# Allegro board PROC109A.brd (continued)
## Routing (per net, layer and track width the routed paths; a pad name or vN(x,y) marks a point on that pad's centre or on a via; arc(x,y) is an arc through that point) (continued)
VBAT_XDS: length 4.1
  BOTTOM w0.178: 18.11,-43.99 U37.68
  BOTTOM w0.33: R249.2 C208.1 17.42,-44.68 18.11,-43.99
VBUS_DETECT: length 1.7
  TOP w0.135: R113.1 14.12,-46.49 U20.4
VBUS_TYPEC: length 6.9
  TOP w0.254: J10.B4 19.77,-58.18 J10.A9 19.77,-55.97 v1(19.61,-55.8) ; J10.B9 17.27,-58.18 J10.A4 17.27,-56.17 v1(16.73,-55.63) ; C70.1 20.43,-54.86
  BOTTOM w0.381: J10.B4 19.72,-57.71 ; J10.B9 17.32,-57.71
  vias: v1(15.46,-54.36) v1(15.46,-55.63) v1(16.48,-54.33) v1(19.68,-50.8) v1(19.68,-52.07) v1(19.84,-53.09) v1(21.34,-52.07)
VBUS_XDS_USB: length 43.5
  TOP w0.203: U24.10 U24.1
  TOP w0.254: TP27.1 2.58,-42.64 8.06,-42.64 v1(9.14,-41.55) ; 9.73,-51.28 9.49,-51.52 U24.10
  TOP w0.381: J20.1 6.48,-52.29 6.81,-51.97
  BOTTOM w0.33: U38.6 11.57,-42.02 ; 10.16,-42.16 11.32,-43.32 U38.4
  BOTTOM w0.381: R222.2 R219.1
  BOTTOM w0.635: R222.2 15.49,-31.27
  BOTTOM w0.762: v1(8.08,-50.85) v1(9.35,-50.85) 11.15,-49.05 11.15,-45.31 9.14,-43.31 v1(9.14,-41.55) 10.16,-40.54 10.16,-38.79 9.37,-38 9.37,-34.09 10.77,-32.69 14.07,-32.69 15.49,-31.27
VCC3V3_TA: length 96.8
  TOP w0.178: v1(28.57,-23.02) U4.2 29.37,-22.73 29.54,-22.56
  TOP w0.203: v1(5.08,-32.72) 5.49,-33.12 TP49.1
  TOP w0.33: v1(30.96,-20.6) C5.1 U4.1
  TOP w0.381: R34.2 26.37,-25.87 v1(26.37,-26.62) ; U9.5 4.21,-28.87 v1(3.94,-28.6) ; R28.2 26.39,-24.35 v1(26.39,-23.57) ; v1(10.4,-27.2) v1(10.4,-25.32) v1(10.4,-23.44) v1(10.4,-21.56) v1(10.4,-19.68) ; v1(5.08,-32.72) 4.65,-32.72 v1(4.01,-32.08) 4.01,-31.11 4.31,-30.82 U9.8
  TOP w0.508: v1(26.39,-23.57) 26.39,-22.87 R17.2 ; R70.2 R67.2 R53.2 ; R34.2 R28.2
  L03_SIG1 w0.381: v1(10.4,-25.32) 11.3,-25.32 12.24,-24.38 12.85,-24.38 13.67,-23.57 14.99,-23.57 15.29,-23.27 18.78,-23.27 19.08,-23.57 v1(26.39,-23.57) 28.02,-23.57 v1(28.57,-23.02) ; v1(6.55,-40.36) 4.01,-37.82 v1(4.01,-32.08) ; v1(5.08,-32.72) 4.45,-32.08 v1(4.01,-32.08) ; v1(4.01,-32.08) 3.94,-32 v1(3.94,-28.6) 8.18,-28.6 9.58,-27.2 v1(10.4,-27.2)
  L04_PWR1 w0.381: v1(7.49,-48.64) v1(9.27,-48.64) 9.27,-47.45 v1(9.3,-47.42)
  BOTTOM w0.254: U26.15 23.72,-19.92 23.6,-20.04 ; U26.14 23.85,-20.42 23.75,-20.32 ; C146.1 7.57,-38.86 ; C155.1 7.57,-39.75
  BOTTOM w0.33: U28.5 C88.1 33.45,-22.29 ; C85.1 22.43,-21.29 v1(22.53,-21.39)
  BOTTOM w0.381: v1(7.49,-48.64) 8.33,-48.64 C243.1 8.44,-48.64 v1(9.27,-48.64) 9.27,-48.02 9.3,-47.99 v1(9.3,-47.42) ; R209.2 v1(10.4,-27.2)
  BOTTOM w0.508: 33.45,-22.29 32.65,-22.29 v1(30.96,-20.6) ; R182.1 12.07,-20.05 11.71,-19.68 v1(10.4,-19.68) R178.1 ; R196.2 12.07,-23.88 11.63,-23.44 v1(10.4,-23.44) R189.2 ; R186.1 v1(10.4,-21.56) 11.84,-21.56 12.07,-21.8 R187.1 ; R197.2 v1(10.4,-25.32) 11.71,-25.32 12.07,-25.69 R202.2 ; R191.2 24.94,-25.19 v1(26.37,-26.62)
VCC3V3_XDS: length 93.8
  TOP w0.254: v1(37.57,-55.27) 37.57,-56.67 TP35.1 ; v1(27.28,-44.58) 27.28,-44.07 27.52,-43.83 R108.2 ; C44.1 U16.7 ; R109.2 v1(29.84,-43.05)
  TOP w0.33: v1(67.85,-50) 68.12,-49.73 68.33,-49.73 C60.1 68.44,-49.87 68.44,-50.19 68.09,-50.54 U25.16 ; v1(25.07,-40.53) C44.1
  TOP w0.381: 38.86,-41.2 40.28,-42.62 40.28,-52.55 v1(37.57,-55.27) ; R101.2 v1(24.99,-41.55) ; R100.2 v1(23.52,-41.55) ; v1(25.22,-48.26) 25.22,-47.02 25.43,-46.81 ; R98.2 v1(20.5,-41.55) ; R99.2 v1(22.05,-41.55)
  L05_GND2 w0.381: v1(58.81,-52.86) 59.29,-52.37 66.52,-52.37 67.85,-51.04 v1(67.85,-50)
  BOTTOM w0.178: v1(17.78,-34.98) 17.78,-35.01 17.96,-35.19 U37.90 ; U37.52 25.5,-47.8 25.63,-47.93 ; C191.1 35.81,-43.59 35.81,-43.59 U37.28 ; U37.79 17.94,-39.59 ; 27.1,-30.23 U37.113 ; U37.51 25.9,-47.77 ; U37.16 35.75,-38.79 35.75,-38.79 ; v1(30.7,-32.44) 30.7,-32.43 U37.122 ; U42.8 66.21,-53.71 65.91,-53.4 65.91,-53.01 65.73,-52.83 C260.1 ; v1(27.28,-44.58) 27.55,-44.85 27.55,-45.73 27.5,-45.78 U37.47 ; U37.26 36.08,-42.79 C180.1 ; C121.1 36.67,-35.19 U37.7 ; v1(22.02,-29.95) 22.3,-30.23 U37.101 ; 17.73,-43.59 U37.69 ; 35.94,-35.48 35.84,-35.59 U37.8 ; 30.71,-47.9 30.7,-47.9 U37.39
  BOTTOM w0.254: U45.16 36.23,-55.66 36.44,-55.87 C262.1 v1(37.57,-55.27) ; 14.82,-42.02 14.39,-42.02 U38.1 ; v1(17.04,-42.39) 17.04,-42.9 17.73,-43.59
  BOTTOM w0.33: 17.94,-39.59 17.88,-39.65 C154.1 16.47,-39.65 v1(15.88,-40.24) ; 35.75,-38.79 36.4,-38.79 C151.1 36.98,-38.81 v1(36.98,-38.81) ; v1(31.62,-47.96) 31.62,-48.54 31.45,-48.72 C240.1 30.71,-47.9 ; 27.1,-30.23 26.95,-30.08 C104.1 27.51,-29.44 v1(27.51,-29.44) ; 38.44,-34.62 v1(36.68,-34.62) C121.1 ; v1(58.81,-52.86) 59.35,-52.86 59.48,-52.73 64.24,-52.73 64.34,-52.83 C260.1 ; v1(25.22,-48.26) 25.5,-48.54 C242.1 26.09,-47.96 25.9,-47.77 ; v1(17.04,-42.39) C181.1 C182.1 15.35,-41.71 15.8,-41.25 R246.1
  BOTTOM w0.381: v1(15.93,-46.58) 15.73,-46.58 15.35,-46.2 R249.1 ; 38.44,-34.62 38.7,-34.62 R235.1
  vias: v1(14.61,-40.24) v1(14.61,-41.51) v1(36.14,-44.2) v1(36.17,-41.96)
VCC_5V0_CAN: length 4.2
  TOP w0.203: v1(165.84,-52.02) 164.92,-52.02 TP50.1
  BOTTOM w0.254: v1(165.84,-52.02) R270.2
  BOTTOM w0.33: U44.3 C257.1 R270.2
VDD_1V1: length 25.7
  TOP w0.254: U19.6 v1(144.35,-45.89) C55.1 ; v1(133.99,-45.48) 133.99,-45.49 133.98,-45.5 C56.1 134.64,-46.03 134.78,-45.89 U19.31 ; C17.1 v1(144.35,-26.84) U7.6 ; v1(138.07,-32.18) 137.52,-32.18 C34.1 137.51,-31.78 138.18,-31.11 U7.39 ; v1(138.07,-51.21) 138.06,-51.22 C61.1 137.51,-50.57 138.18,-49.89 U19.39 ; v1(133.99,-26.43) 133.99,-26.44 133.98,-26.45 C19.1 134.64,-26.98 134.78,-26.84 U7.31
  TOP w0.381: TP30.1 125.19,-46.22 125.19,-46.46 125.23,-46.5 125.23,-46.56 125.2,-46.59 125.21,-47.38 125.19,-47.38 v1(125.19,-47.42)
  BOTTOM w0.229: U39.9 125.49,-44.39 125.73,-44.63 ; 125.6,-45.01 125.48,-44.89 U39.10
  BOTTOM w0.254: v1(133.99,-26.43) 133.96,-26.45 C97.1 ; C113.1 138.02,-32.23 v1(138.07,-32.18)
  BOTTOM w0.33: C96.1 144.34,-26.85 v1(144.35,-26.84) C17.1 ; C217.1 144.34,-45.9 v1(144.35,-45.89) C55.1 ; C228.1 134,-46.05 C56.1 133.98,-45.49 v1(133.99,-45.48) ; C256.1 138,-51.28 v1(138.07,-51.21) ; C98.1 133.96,-28.06 C97.1 ; C229.1 126.19,-47.19
  BOTTOM w0.508: C222.1 125.7,-46.05
  vias: v1(125.19,-48.69) v1(126.46,-48.69)
VDD_1V1_SS: length 1.7
  BOTTOM w0.203: C183.1 126.1,-43.39 U39.7
VDD_1V8: length 84.1
  TOP w0.203: TP5.1 63.58,-21.67 40.82,-21.67 37.83,-18.68 33.24,-18.68 32.33,-19.58 31.29,-19.58 30.73,-19.02 29.9,-19.02 26.9,-22.02 25.21,-22.02 24.85,-22.38 23.83,-22.38 23.55,-22.1 22.92,-22.1 19.94,-25.07 v1(19.94,-26.75)
  TOP w0.254: v1(66.17,-23.37) 66.17,-23.75 R30.2 65.1,-23.48 v1(65.1,-23.36) 64.69,-23.36 R29.2 ; C30.2 76.61,-32.74 76.87,-33.01 U11.5
  TOP w0.305: U18.F14 79.35,-42.27 v2(79.35,-41.84)
  TOP w0.33: v1(77.37,-32.21) 77.37,-32.18 77.04,-31.85 C30.2
  TOP w0.381: v1(92.18,-44.12) v1(92.99,-44.12)
  L03_SIG1 w0.152: 77.33,-41.29 77.44,-41.19 78.7,-41.19 v2(79.35,-41.84)
  L03_SIG1 w0.254: 77.33,-41.29 73.11,-41.29 72.71,-40.89 71.35,-40.89 68.88,-43.36 v1(68.3,-43.36)
  L03_SIG1 w0.381: v1(65.1,-23.36) 65.11,-23.37 v1(66.17,-23.37)
  L04_PWR1 w0.254: v1(92.18,-44.12) 92.04,-43.99 92.04,-40.73 91.31,-40
  L04_PWR1 w0.508: v1(77.37,-32.21) 77.06,-32.51 v1(77.06,-33.63)
  BOTTOM w0.135: v1(91.72,-46.28) v1(92.99,-46.28)
  BOTTOM w0.305: C162.1 78.63,-41.31 78.63,-41.31 79.15,-41.84 v2(79.35,-41.84)
  BOTTOM w0.381: R198.1 v1(19.94,-26.75) ; FB1.1 77.37,-31.46 v1(77.37,-32.21) 78.09,-32.93 FB2.1
  BOTTOM w0.508: v1(77.06,-33.63) 77.14,-33.56 FB2.1
  vias: v1(64.9,-22.1) v1(66.17,-22.1) v1(68.76,-49.23)
VDD_1V8_CT: length 3.8
  BOTTOM w0.254: U27.5 17.74,-16.86 18.71,-15.89 C80.1
VDD_1V8_ENABLE: length 31.4
  TOP w0.254: U10.8 42.79,-30.57 v1(42.55,-30.81) 39.29,-30.81 38.81,-30.33 38.81,-24.71 41.05,-22.48 56.55,-22.48 57.07,-23 R31.1
  BOTTOM w0.381: R224.1 v1(42.55,-30.81)
VDD_1V8_R: length 1
  TOP w0.33: 62.61,-26.43 U5.1 ; C20.1 64.67,-26.31
VDD_1V8_SENSE: length 5.9
  BOTTOM w0.135: U27.10 19.57,-21.6 19.94,-21.97 R198.2 R199.1
VDD_2V5: length 21.6
  TOP w0.254: U19.3 v1(144.35,-47.39) C58.1 ; C11.1 v1(144.35,-25.34) U7.9 ; U19.9 v1(144.35,-44.39) C53.1 ; C23.1 v1(144.35,-28.34) U7.3
  TOP w0.381: v1(125.24,-36.7) 124.54,-36.7 123.16,-35.33 TP20.1 R81.2
  BOTTOM w0.229: U33.10 125.48,-34.17 125.6,-34.29 ; 125.73,-33.91 125.49,-33.67 U33.9
  BOTTOM w0.33: C107.1 145.03,-29 144.91,-28.88 144.95,-28.84 C23.1 v1(144.35,-28.34) 143.8,-28.34 C100.1 ; v1(144.32,-49) 144.68,-48.64 C238.1 145.03,-47.98 144.95,-47.89 C58.1 v1(144.35,-47.39) 144.32,-47.42 C231.1 ; C130.1 126.28,-36.47 ; C11.1 v1(144.35,-25.34) ; C53.1 v1(144.35,-44.39)
  BOTTOM w0.381: v1(144.22,-29.97) 144.6,-29.59 C107.1
  BOTTOM w0.508: C125.1 125.71,-35.33 125.7,-35.33
  vias: v1(125.24,-37.97) v1(126.46,-37.97)
VDD_2V5_PG: length 20.2
  TOP w0.203: v1(115.7,-35.31) 119.17,-35.31 119.19,-35.33 R81.1
  TOP w0.254: v1(120.55,-33.54) 119.78,-34.31 R81.1
  BOTTOM w0.203: v1(120.55,-33.54) 121.34,-33.54 121.34,-33.32 121.49,-33.17 U33.3 ; v1(115.7,-35.31) 115.7,-39.62 117.98,-41.91 120.37,-41.91 121.35,-42.89 U39.5
VDD_2V5_SS: length 1.7
  BOTTOM w0.203: C111.1 126.1,-32.67 U33.7
VDD_CORE_0V85: length 122.9
  TOP w0.102: 81.38,-44.81 80.89,-44.33 U18.J10
  TOP w0.152: U18.R12 83.89,-43.3 83.41,-42.82 ; U18.R10 83.89,-44.33 v2(83.37,-44.86) 82.89,-44.38 U18.N10
  TOP w0.178: U18.J12 80.7,-43.09 v2(80.41,-42.77)
  TOP w0.254: v2(85.36,-41.77) 85.39,-41.74 U18.V16 ; TP23.1 56.49,-38.1 v1(56.49,-39.75) ; C48.1 56.62,-42.42 v1(56.49,-42.29) ; U18.L9 v2(81.89,-45.28) ; C49.1 57.76,-42.9 v1(57.76,-42.29)
  TOP w0.305: v2(81.39,-44.83) 81.38,-44.81 U18.J9 ; U18.L13 81.5,-42.82 v2(81.46,-42.77) 81.39,-42.71 U18.K14 ; U18.H15 80.37,-41.79 v2(79.87,-41.79) ; U18.H8 80.41,-45.3 v2(80.41,-44.83) ; U18.K11 81.39,-43.37 v2(81.4,-43.36) 80.94,-43.36 U18.J12 ; U18.N9 82.88,-44.82 v2(82.88,-45.28) 82.85,-45.31 U18.M8 ; v2(79.91,-45.86) 79.89,-45.87 U18.G6 U18.G5 ; U18.R9 83.89,-45.22 v2(83.94,-45.26) 83.45,-45.26 U18.P8 ; U18.R13 83.41,-42.82 v2(83.37,-42.77) 83.39,-42.75 U18.P14 ; v2(80.41,-44.27) 80.45,-44.31 U18.J10 ; U18.F11 79.39,-44.26 v2(79.41,-44.27) 79.45,-44.31 U18.G10 ; v2(82.39,-42.77) U18.M14
  TOP w0.508: v1(51.26,-50.16) R130.1 C62.1 ; 55.33,-39.88 55.08,-40.13 R96.1 55.08,-42.04 55.46,-42.42
  L03_SIG1 w0.254: v1(23.22,-18.57) 27.55,-18.57 31.24,-22.26 31.24,-27 35.51,-31.27 36.68,-31.27 39.45,-34.04 54.97,-34.04 56.49,-35.56 v1(56.49,-39.75)
  L04_PWR1 w0.102: v2(83.37,-42.77) 83.92,-42.77 84.4,-42.29
  L04_PWR1 w0.254: v1(79.35,-52.12) 78.84,-52.12 78.26,-52.7 72.77,-52.7 70.84,-50.77 70.84,-49.4 69.93,-48.49 63.7,-48.49 63.37,-48.82 52.6,-48.82 v1(51.26,-50.16)
  L04_PWR1 w0.305: v2(85.36,-41.77) 85.25,-41.77 84.73,-42.29 84.4,-42.29
  BOTTOM w0.254: v2(81.4,-43.36) 81.4,-42.78 v2(81.46,-42.77) 81.56,-42.87 C187.1
  BOTTOM w0.305: v2(81.39,-44.83) 81.5,-44.73 C199.1 ; C211.1 83.32,-44.91 v2(83.37,-44.86) ; C211.1 83.84,-45.36 v2(83.94,-45.26) ; C211.1 82.97,-45.36 v2(82.88,-45.28) 82.8,-45.36 C212.1 81.98,-45.36 v2(81.89,-45.28) ; C214.1 80.15,-46.1 v2(79.91,-45.86) 79.91,-46.78 C227.1 ; C187.1 82.29,-42.87 v2(82.39,-42.77) 82.5,-42.87 C186.1 83.26,-42.87 v2(83.37,-42.77) ; v2(80.41,-42.77) 80.51,-42.87 C188.1 81.36,-42.87 v2(81.46,-42.77) ; v2(80.41,-44.27) v2(80.41,-44.83) 80.47,-44.77 C200.1
  BOTTOM w0.33: C227.1 79.67,-46.79 79.65,-46.8 79.65,-46.8 79.36,-47.09 79.36,-47.1 79.2,-47.25 79.2,-47.52 ; v2(85.36,-41.77) 85.36,-41.66 C165.1 ; v2(79.41,-44.27) 79.47,-44.34 C201.1 80.35,-44.34 v2(80.41,-44.27) ; C163.1 79.96,-41.7 v2(79.87,-41.79)
  BOTTOM w0.381: v1(80.11,-51.59) 79.91,-51.38 C255.1 79.15,-51.92 v1(79.35,-52.12) ; v1(74.8,-38.91) 74.52,-38.63 C136.1 74.52,-38.2 v1(73.74,-38.2)
  BOTTOM w0.508: C234.1 79.2,-47.52 ; v1(23.22,-18.57) 22.61,-17.96 R176.2
  vias: v1(56.49,-41.02) v1(57.76,-39.75) v1(57.76,-41.02) v1(59.03,-39.75) v1(59.03,-41.02) v1(59.03,-42.29) v1(60.3,-39.75) v1(60.3,-41.02) v1(60.3,-42.29) v1(76.2,-38.73) v1(80.14,-49.4) v1(80.06,-50.39) v1(80.8,-52.12)
VDD_CORE_0V85_EN: length 36.4
  TOP w0.254: R127.1 48.68,-50.15 48.94,-49.89 v1(48.94,-49.43)
  TOP w0.381: v1(62.41,-23.77) R29.1 63.23,-24.8 62.91,-25.13 U5.3
  BOTTOM w0.203: v1(62.41,-23.77) 61.39,-23.77 60.19,-24.98 60.19,-32.85 49.71,-43.33 49.71,-45.77 48.94,-46.54 v1(48.94,-49.43)
VDD_CORE_0V85_FB: length 4.4
  TOP w0.254: U21.2 49.64,-47.31 49.64,-47.31 49.64,-48.75 R124.1 R130.2 C62.2
VDD_CORE_0V85_H_SENSE: length 5.9
  TOP w0.135: v1(20.47,-16.54) 21.3,-16.54 R6.1
  BOTTOM w0.135: U27.6 19.5,-19.6 19.68,-19.42 19.68,-17.32 v1(20.47,-16.54) 21.28,-16.54 R175.2
VDD_CORE_0V85_L_SENSE: length 5.1
  TOP w0.135: R6.2 20.82,-17.61 v1(20.47,-17.96)
  BOTTOM w0.135: U27.7 19.5,-20.1 20.04,-19.56 20.04,-18.39 v1(20.47,-17.96) R176.1
VDD_CORE_0V85_PG: length 62
  TOP w0.254: R112.1 U21.8 ; Q3.3 v1(3.01,-41.85)
  TOP w0.381: v1(42.8,-43.31) 42.8,-45.24 43.37,-45.81 R112.1
  L03_SIG1 w0.381: v1(42.8,-43.31) 41.22,-43.31 38.57,-40.66 38.57,-34.79 36.82,-33.03 32.27,-33.03 31.5,-33.8 27.37,-33.8 26.97,-33.41 21.53,-33.41 21.24,-33.7 15.39,-33.7 15,-33.3 12.72,-33.3 7.11,-38.92 7.11,-40.77 6.6,-41.27 3.59,-41.27 v1(3.01,-41.85)
VDD_CORE_0V85_R: length 3.8
  TOP w0.254: 53.85,-42.42 53.32,-42.95 C50.1
  TOP w0.508: 53.72,-39.88 54.1,-40.26 R96.2 54.1,-42.17 53.85,-42.42
VDD_CORE_0V85_SW: length 4.8
  TOP w0.254: 50.56,-44.41 50.56,-44.54 50.14,-44.96 U21.6
  TOP w0.762: 50.56,-44.41 L2.1
VDDA_1P8_USB0: length 6.6
  TOP w0.152: U18.U15 84.89,-41.88 v2(85.36,-42.35)
  TOP w0.254: TP47.1 92.2,-40.61 v1(92.53,-40.94)
  BOTTOM w0.127: C177.1 86.69,-42.38
  BOTTOM w0.152: v2(85.36,-42.35) 85.73,-42.72 86.35,-42.72 86.69,-42.38
  BOTTOM w0.254: FB5.2 90.56,-42.1 91.24,-41.43 91.62,-41.43 92.1,-40.94 v1(92.53,-40.94)
  BOTTOM w0.33: C176.1 C177.1
VDDA_1V8: length 105.6
  TOP w0.254: v1(32.59,-17.98) 34.14,-17.98 TP40.1
  TOP w0.305: U18.F18 79.82,-40.32 v2(79.85,-40.35) ; U18.H14 79.93,-42.32 v2(79.89,-42.35)
  TOP w0.33: v1(32.59,-17.98) C4.1 32.57,-17.4 31.91,-16.74 U1.5
  TOP w0.381: v1(12.82,-22.13) 12.59,-22.13 12.21,-21.75 R15.2
  L03_SIG1 w0.381: v1(12.82,-22.13) 12.82,-20.44 14.73,-18.53 21.7,-18.53 22.25,-17.98 v1(32.59,-17.98) 32.59,-27.33 34.04,-28.78 35.48,-28.78 36.09,-28.17 37.21,-28.17 38.33,-29.29 49.84,-29.29 50.2,-29.65 55.61,-29.65 56.98,-31.02 71.66,-31.02 74.93,-34.29 77.55,-34.29 78.28,-33.55 v1(80.59,-33.55) 79.68,-34.47 79.68,-36.3 v1(79.96,-36.58)
  L05_GND2 w0.203: v2(79.89,-42.35) 80.27,-41.97 80.27,-41.21 79.85,-40.79 v2(79.85,-40.35)
  BOTTOM w0.305: C153.1 78.7,-39.19 79.05,-39.54 79.05,-39.7 79.69,-40.35 v2(79.85,-40.35)
  BOTTOM w0.33: 79.4,-35.48 C126.1 ; 79.33,-36.86 78.7,-37.49 C135.1 C144.1 C153.1
  BOTTOM w0.381: 79.32,-36.86 79.33,-36.86 C126.1
  BOTTOM w0.508: C126.1 79.33,-34.84 79.71,-34.47 79.69,-34.45 FB2.2 79.7,-33.55 v1(80.59,-33.55)
VDDA_3P3_USB0: length 12.8
  TOP w0.152: v2(84.42,-41.83) 84.89,-41.35 U18.U16
  TOP w0.254: TP45.1 90.22,-38.84 v1(89.81,-38.84)
  L03_SIG1 w0.254: v1(89.81,-38.84) 88.9,-38.84 86.4,-41.34 84.97,-41.34 84.48,-41.83 v2(84.42,-41.83)
  BOTTOM w0.152: C178.1 84.85,-41.38 84.42,-41.81 v2(84.42,-41.83)
  BOTTOM w0.33: C156.1 87.59,-39.62 87.27,-39.93 C157.1
  BOTTOM w0.508: v1(89.81,-38.84) 89.65,-39 FB4.2 89,-39.78 88.84,-39.62 C156.1
VDDA_3V3: length 19.1
  TOP w0.102: v2(80.89,-42.3) 81.12,-42.08 81.13,-42.08 U18.K15
  TOP w0.254: v1(70.79,-37.24) 70.79,-37.22 70.38,-36.81 70.38,-35.76 TP43.1
  L03_SIG1 w0.152: v1(70.79,-37.24) 71.25,-37.69 77.29,-37.69 79.28,-39.68 79.28,-40.44 80.51,-41.68 80.51,-41.93 80.88,-42.3 v2(80.89,-42.3)
  BOTTOM w0.305: v2(80.89,-42.3) 80.6,-42.3 C174.1
  BOTTOM w0.33: FB3.2 C142.1
  BOTTOM w0.508: FB3.2 71.3,-38.19 70.79,-37.68 v1(70.79,-37.24)
VDDA_ADC: length 18.9
  TOP w0.203: v1(80.39,-32.05) 80.39,-32.69 TP48.1
  TOP w0.305: U18.G17 U18.H17 80.41,-40.8 v2(80.41,-40.35)
  L03_SIG1 w0.381: v1(80.39,-32.05) 81.45,-33.12 81.45,-34.08 80.79,-34.74 80.79,-35.48 81.11,-35.8 81.11,-38.84 80.9,-39.05 80.9,-39.92 80.47,-40.35 v2(80.41,-40.35)
  BOTTOM w0.203: v2(80.41,-40.35) 80.74,-40.02 80.74,-39.38 80.7,-39.34
  BOTTOM w0.254: C147.1 80.56,-39.19 80.7,-39.34
  BOTTOM w0.33: C147.1 C148.1 ; C116.1 81.39,-32.7 81.39,-32.39 81.06,-32.05 v1(80.39,-32.05)
  BOTTOM w0.508: v1(80.39,-32.05) 80.24,-32.21 79.61,-32.21 79.31,-31.9 FB1.2 C109.1
VDDA_PLL0: length 13.4
  TOP w0.254: TP41.1 90.22,-47.55 v1(91.06,-47.55)
  TOP w0.305: v2(83.37,-43.36) 83.32,-43.32 U18.N12
  L03_SIG1 w0.102: 86.39,-43.92 85.75,-43.92 85.54,-44.13 85.2,-44.13 84.84,-43.76 83.77,-43.76 v2(83.37,-43.36)
  L03_SIG1 w0.254: 89.05,-44.12 88.06,-44.12 87.86,-43.92 86.39,-43.92
  L03_SIG1 w0.381: v1(90.3,-44.12) v1(89.46,-44.12) 89.05,-44.12
  BOTTOM w0.254: v1(91.06,-47.55) 91.06,-46.06 90.95,-45.95 90.95,-45.8 90.26,-45.11 FB7.2
  BOTTOM w0.305: C185.1 v2(83.37,-43.36)
  BOTTOM w0.33: C206.1 87.96,-44.87 87.95,-44.88 C204.1
VDDA_PLL1: length 12.8
  TOP w0.305: v2(79.39,-44.83) 79.88,-44.83 U18.G9
  TOP w0.381: TP44.1 73.99,-48.29 v1(74.96,-47.32)
  L03_SIG1 w0.254: v2(79.39,-44.83) 77.44,-44.83 v1(74.96,-47.32)
  BOTTOM w0.254: FB9.2 72.09,-48.36 72.17,-48.28 C241.1 73.49,-48.28 73.52,-48.31 C236.1 74.02,-48.3 74.41,-47.9 74.41,-47.84 v1(74.96,-47.32) ; C210.1 79.37,-44.83 v2(79.39,-44.83)
VDDA_PLL2: length 14.2
  TOP w0.254: v1(71.81,-43.46) 72.62,-43.46 TP46.1
  TOP w0.381: U18.G12 79.46,-43.32 v2(79.42,-43.36)
  L03_SIG1 w0.254: v1(71.81,-43.46) 72.21,-43.87 75.87,-43.87 77.13,-42.61 78.08,-42.61 78.25,-42.77 78.81,-42.77 79.39,-43.36 v2(79.42,-43.36)
  BOTTOM w0.33: C194.1 73.76,-43.98 73.31,-43.53 C193.1 72.5,-43.46 v1(71.81,-43.46) 71.39,-43.46 FB6.2
  BOTTOM w0.356: v2(79.42,-43.36) 79.07,-43.36 78.87,-43.16 C184.1
VDDA_TEMP: length 19.2
  TOP w0.102: v2(80.41,-43.36) 79.95,-43.81 U18.G11
  TOP w0.254: TP42.1 v1(71.88,-45.34) ; U18.M11 v2(82.39,-44.27)
  L03_SIG1 w0.152: 77.55,-42.96 78.01,-42.96 78.25,-43.21 78.54,-43.21
  L03_SIG1 w0.254: v2(82.39,-44.27) 81.91,-43.79 80.84,-43.79 v2(80.41,-43.36) 79.98,-43.79 79.12,-43.79 78.54,-43.21 ; 77.55,-42.96 76.09,-44.42 72.8,-44.42 v1(71.88,-45.34)
  BOTTOM w0.254: v2(80.41,-43.36) 80.37,-43.36 80.06,-43.05 C190.1
  BOTTOM w0.305: v2(82.39,-44.27) 82.55,-44.12 C198.1
  BOTTOM w0.33: C225.1 73.39,-46.02 73.51,-45.9 C224.1
  BOTTOM w0.508: FB8.2 71.87,-46.18 72.03,-46.02 C225.1
VDDC_1V2_XDS: length 37.8
  TOP w0.254: v1(18.06,-37.39) 34.87,-37.39 37.47,-34.8 37.47,-33.5 34.75,-30.78 v1(33.86,-30.78)
  BOTTOM w0.178: U37.87 18.16,-36.39 ; U37.115 27.9,-30.2
  BOTTOM w0.33: 27.9,-30.2 28.1,-30.01 C105.1 C102.1 33.14,-29.52 33.86,-30.24 v1(33.86,-30.78) ; v1(18.06,-37.39) 18.01,-37.34 17.98,-37.34 C132.1 17.82,-36.39 18.16,-36.39
VDDSHV_3V3: length 55.9
  TOP w0.152: U18.U8 84.41,-44.84 v2(84.36,-44.84) ; v2(83.85,-45.82) 83.85,-45.86 U18.P6 ; v2(81.89,-45.86) 82.35,-46.31 U18.M6 ; U18.E9 78.89,-44.82 v2(78.44,-45.28) ; 83.94,-40.82 v2(84.39,-41.27) ; U18.E7 78.89,-45.75 78.59,-45.44 78.59,-45.43 78.47,-45.31
  TOP w0.254: U18.C13 78.33,-42.37 78.39,-42.37 ; v1(84.58,-52.2) 84.58,-51.59 TP52.1 ; U18.R17 83.94,-40.82
  TOP w0.305: U18.T11 U18.U11 84.89,-43.4 v2(84.94,-43.36) ; U18.P5 U18.P6 ; v2(82.88,-41.77) 82.88,-41.32 U18.N16 U18.N17 ; U18.E14 78.45,-42.32 v2(78.43,-42.34) 78.39,-42.37 U18.D13 ; U18.L6 v2(81.89,-45.86) ; U18.U8 U18.U7 ; U18.E8 78.47,-45.31 v2(78.44,-45.28) ; U18.T17 v2(84.39,-41.27) ; v2(78.44,-41.77) 78.48,-41.82 U18.E15 ; v2(84.36,-44.84) 84.36,-45.04 84.39,-45.07 U18.T8
  L03_SIG1 w0.33: v2(84.39,-41.27) 84.39,-40.6 84.64,-40.36 84.64,-37.35 84.3,-37.02 v1(84.3,-36.47)
  L04_PWR1 w0.152: v2(83.85,-45.82) 83.95,-45.82 84.36,-45.41 v2(84.36,-44.84)
  L04_PWR1 w0.254: v2(84.39,-41.27) 84.84,-41.27 ; v2(84.36,-44.84) 84.83,-44.84
  BOTTOM w0.178: v2(83.85,-45.82) 83.94,-45.82 84.29,-45.47 C213.1
  BOTTOM w0.254: C205.1 85.21,-43.36 v2(84.94,-43.36) ; v2(81.89,-45.86) 81.89,-45.98 82.25,-46.34 82.57,-46.34 82.71,-46.48 83.54,-46.48 ; 84.46,-48.54 84.45,-48.54 84.45,-48.42
  BOTTOM w0.305: C215.1 81.6,-46.15 v2(81.89,-45.86) ; C235.1 84.45,-48.42 84.45,-47.15 83.85,-46.55 v2(83.85,-45.82) ; C203.1 85.27,-44.82 85.17,-44.82 85.16,-44.84 v2(84.36,-44.84) ; C175.1 82.69,-41.58 v2(82.88,-41.77) 82.88,-41.31 83.25,-40.95 84.07,-40.95 v2(84.39,-41.27) 84.39,-40.57 C158.1 84.39,-40.34 84.39,-39.03 C145.1 ; C202.1 78.44,-45.13 v2(78.44,-45.28)
  BOTTOM w0.33: C140.1 C141.1 C134.1 84.21,-36.47 v1(84.3,-36.47) ; C140.1 C133.1 84.61,-36.78 v1(84.3,-36.47) ; C140.1 C145.1 ; v1(84.3,-35.66) v1(84.3,-36.47)
  BOTTOM w0.381: C167.1 77.01,-41.82 77.53,-42.34 v2(78.43,-42.34) 78.43,-41.78 v2(78.44,-41.77)
  BOTTOM w0.508: 76.28,-47.9 75.46,-48.72 75.46,-52.22 76.17,-52.93 83.85,-52.93 v1(84.58,-52.2)
  vias: v1(85.6,-52.2)
VDDSHV_SDIO: length 34.8
  TOP w0.305: U18.J17 80.94,-40.86 v2(81.41,-40.86) ; U18.L17 U18.L16 81.89,-41.73 v2(81.85,-41.77)
  TOP w0.381: v1(93.29,-24.26) 93.29,-24.26 R21.2 ; R19.2 89.05,-24.26 88.67,-23.88 v1(88.67,-23.04)
  L03_SIG1 w0.254: v2(81.41,-40.86) 81.41,-41.33 v2(81.85,-41.77)
  L04_PWR1 w0.381: v1(81.38,-35) 81.38,-27.81 86.16,-23.04 v1(88.67,-23.04)
  BOTTOM w0.203: C143.1 81.36,-39.27 81.05,-39.58 81.05,-40.14 C160.1
  BOTTOM w0.33: C160.1 81.37,-40.46 81.37,-40.54 81.41,-40.58 v2(81.41,-40.86) 81.39,-40.88 C172.1 ; v1(81.38,-35) 81.38,-36.05 80.54,-36.89 80.54,-37.99 C143.1
  BOTTOM w0.381: v1(88.67,-23.04) 88.67,-23.09 88.65,-23.11 R194.2 R193.2 R192.2 92.75,-23.72 v1(93.29,-24.26)
BOARD_POWER_EN: length 5.2
  TOP w0.254: R84.2 R85.1 42.3,-35.15 43.29,-34.16 43.29,-32.8 43.43,-32.67 U10.1
BOOTMODE0: length 2.1
  TOP w0.135: R39.1 87.12,-27.47 v1(87.12,-28.17) 87.12,-28.84 R55.2
  BOTTOM w0.135: R208.2 87.13,-28.16 v1(87.12,-28.17)
BOOTMODE0_R: length 47.7
  TOP w0.102: U18.R21 83.95,-38.76 83.95,-38.4 84.2,-38.15 84.2,-37.97
  TOP w0.135: 84.2,-37.97 84.2,-37.54 84.78,-36.96 84.78,-35.34 87.12,-32.99 v1(87.12,-30.81) 87.12,-29.83 R55.1
  L03_SIG1 w0.121: v1(115.11,-29.44) 114.55,-30 114.55,-30.73 110.76,-34.53 105.39,-34.53 103.38,-32.51 99.69,-32.51 99.19,-33.02 97.92,-33.02 97.47,-32.58 94.68,-32.58 94.14,-33.12 89.43,-33.12 v1(87.12,-30.81)
  BOTTOM w0.135: v1(115.11,-29.44) 116.44,-28.11 U32.1
BOOTMODE1: length 2
  TOP w0.135: R56.2 88.52,-28.16 v1(88.52,-28.15) 88.52,-28.15 R40.1
  BOTTOM w0.135: R207.2 88.52,-28.15 v1(88.52,-28.15)
BOOTMODE2: length 3.1
  TOP w0.135: v1(91.39,-27.46) 91.38,-27.46 R41.1
  BOTTOM w0.135: R215.2 91.33,-28.85 90.68,-28.2 R206.2 90.72,-27.46 v1(91.39,-27.46)
BOOTMODE2_R: length 59.8
  TOP w0.102: v2(83.94,-39.78) 83.96,-39.82 U18.T19
  L03_SIG1 w0.121: v1(112.57,-29.46) 113.13,-28.91 114.02,-28.91 114.27,-29.16 114.27,-30.63 110.64,-34.27 105.65,-34.27 103.5,-32.13 94.59,-32.13 93.86,-32.86 90.68,-32.86 v1(89.97,-32.15) 88.82,-32.15 87.71,-31.03 87.71,-30.43 87.48,-30.2 86.23,-30.2 85.88,-30.56 85.88,-31.78 83.54,-34.11 83.54,-38.69 83.94,-39.08 v2(83.94,-39.78)
  BOTTOM w0.135: U32.6 114.61,-24.86 112.57,-26.9 v1(112.57,-29.46) ; v1(89.97,-32.15) 90.6,-31.51 90.6,-30.56 91.33,-29.83 R215.1
BOOTMODE3: length 64.8
  TOP w0.135: R42.2 92.82,-26.03 92.99,-25.86 v1(92.99,-25.82) ; v1(33.71,-24.02) 33.7,-24.02 U4.21
  L03_SIG1 w0.121: v1(33.71,-24.02) 33.89,-24.21 39.22,-24.21 40.89,-22.53 75.36,-22.53 75.74,-22.91 81.74,-22.91 82.02,-22.63 86.58,-22.63 88.48,-24.53 88.52,-24.53 90.16,-26.16 90.18,-26.16 90.46,-26.45 91.1,-26.45 91.87,-27.22 92.23,-27.22 92.99,-26.46 v1(92.99,-25.82)
BOOTMODE4: length 65
  TOP w0.135: R59.2 92.83,-28.85 v1(92.14,-28.85) ; U4.20 34.4,-24.52 34.87,-24.99 v1(35.59,-24.99)
  L03_SIG1 w0.121: v1(92.14,-28.85) 91.7,-28.85 90.5,-27.65 90.5,-27.2 89.97,-26.68 89.84,-26.68 89.47,-27.04 89.12,-27.04 88.87,-26.79 88.87,-25.6 88.42,-25.15 87.41,-25.15 86.44,-24.18 83.39,-24.18 82.78,-23.57 75.26,-23.57 74.73,-23.04 67.2,-23.04 65.84,-24.41 57.07,-24.41 56.38,-25.1 39.38,-25.1 39.18,-25.31 35.9,-25.31 v1(35.59,-24.99)
BOOTMODE5: length 61.5
  TOP w0.135: v1(33.71,-25.02) 33.7,-25.02 U4.19 ; v1(89.92,-27.33) 89.92,-28.83 R57.2
  L03_SIG1 w0.121: v1(33.71,-25.02) 34.29,-25.6 39.24,-25.6 39.49,-25.36 56.71,-25.36 57.28,-24.79 65.89,-24.79 67.38,-23.3 74.38,-23.3 74.9,-23.82 82.68,-23.82 83.57,-24.71 85.47,-24.71 87.25,-26.5 88.21,-26.5 89.05,-27.33 v1(89.92,-27.33)
BOOTMODE6: length 61.6
  TOP w0.135: 32.82,-25.52 34.97,-25.52 v1(35.66,-26.21)
  L03_SIG1 w0.121: v1(87.84,-27) 86.51,-27 85.88,-26.37 84.86,-26.37 82.57,-24.08 74.6,-24.08 74.07,-23.55 67.79,-23.55 64.39,-26.95 59.87,-26.95 59,-26.09 55.64,-26.09 55.52,-26.2 49.06,-26.2 48.47,-25.61 39.62,-25.61 39.01,-26.21 v1(35.66,-26.21)
  BOTTOM w0.135: v1(87.84,-27) 87.84,-28.74 87.71,-28.87 R217.2
BOOTMODE7: length 62.1
  TOP w0.135: v1(34.32,-26.11) 34.23,-26.02 U4.17
  L03_SIG1 w0.121: v1(89.43,-28.14) 88.8,-27.51 86.56,-27.51 85.7,-26.64 84.78,-26.64 82.46,-24.33 74.37,-24.33 73.85,-23.81 68.24,-23.81 64.8,-27.25 56.08,-27.25 55.32,-26.49 39.07,-26.49 38.71,-26.85 35.05,-26.85 v1(34.32,-26.11)
  BOTTOM w0.135: R216.2 89.21,-28.85 89.43,-28.63 v1(89.43,-28.14)
BOOTMODE8: length 68.6
  TOP w0.135: v1(37.08,-24.66) 37.08,-25.93 36.02,-27 34.39,-27 33.91,-26.52 U4.16
  L03_SIG1 w0.121: v1(95.02,-28.85) 93.39,-28.85 92.41,-27.88 91.21,-27.88 90.97,-27.63 90.97,-27.26 90.41,-26.7 90.36,-26.7 90.08,-26.42 90.06,-26.42 88.45,-24.82 87.44,-24.82 85.51,-22.89 82.12,-22.89 81.84,-23.17 75.39,-23.17 75.01,-22.79 41.09,-22.79 39.22,-24.66 v1(37.08,-24.66)
  BOTTOM w0.135: v1(95.02,-28.85) 94.3,-28.85 R214.2
BOOTMODE8_R: length 50.6
  TOP w0.102: v2(85.42,-40.82) 84.92,-40.32 U18.U18
  L03_SIG1 w0.121: v1(115.11,-30.56) 110.53,-35.14 109.43,-35.14 109.04,-35.52 107.27,-35.52 106.68,-34.93 101.98,-34.93 101.5,-35.41 v1(93.7,-35.41) 91.59,-35.41 86.18,-40.82 v2(85.42,-40.82)
  BOTTOM w0.135: U32.3 117.99,-26.81 117.13,-25.95 115.5,-25.95 114.68,-26.77 114.68,-30.13 v1(115.11,-30.56) ; R214.1 94.33,-29.83 95.02,-30.52 95.02,-34.09 v1(93.7,-35.41)
BOOTMODE9: length 64.1
  TOP w0.135: R58.2 91.36,-28.85 v1(90.64,-28.85) ; U4.15 33.98,-27.02 v1(34.72,-27.77)
  L03_SIG1 w0.121: v1(90.64,-28.85) 85.69,-28.85 84.36,-27.53 84.36,-26.59 82.43,-24.66 73.2,-24.66 72.63,-24.08 68.78,-24.08 65.35,-27.51 63.78,-27.51 62.97,-28.31 56.03,-28.31 55.32,-27.6 43.6,-27.6 42.88,-26.88 39.23,-26.88 38.79,-27.33 35.16,-27.33 v1(34.72,-27.77)
BOOTMODE9_R: length 50.1
  TOP w0.102: 85.02,-37.97 85.02,-38.27 84.61,-38.68 84.61,-39.04 U18.U20
  TOP w0.135: R58.1 v1(91.37,-30.81) 90.73,-31.45 89.84,-31.45 85.6,-35.69 85.6,-37.39 85.02,-37.97
  L03_SIG1 w0.121: v1(113.74,-29.44) 113.74,-30.8 110.53,-34.02 107.42,-34.02 104.65,-31.24 97.89,-31.24 97.38,-31.75 94.51,-31.75 93.66,-32.61 92.27,-32.61 91.37,-31.7 v1(91.37,-30.81)
  BOTTOM w0.135: U32.4 117.8,-26.16 117.22,-25.58 114.93,-25.58 113.17,-27.34 113.17,-28.42 113.74,-28.99 v1(113.74,-29.44)
BOOTMODE10: length 2.1
  TOP w0.135: R43.1 94.29,-28.16 v1(94.28,-28.16) 94.28,-28.17 94.29,-28.17 R60.2
  BOTTOM w0.135: R205.2 94.31,-28.14 v1(94.28,-28.16)
BOOTMODE10_R: length 47.6
  TOP w0.102: 86.41,-37.97 86.27,-37.97 85.71,-38.53 85.71,-39 U18.V20
  TOP w0.135: R60.1 94.28,-29.83 v1(94.28,-30.81) 94.28,-31.62 93.31,-32.6 91.81,-32.6 90.4,-34.01 88.95,-34.01 87.45,-35.51 87.45,-36.93 86.41,-37.97
  L03_SIG1 w0.121: v1(113.16,-30.56) 113.16,-31.03 110.42,-33.76 107.68,-33.76 104.9,-30.99 97.79,-30.99 97.78,-30.99 97.76,-30.99 97.38,-31.37 94.84,-31.37 v1(94.28,-30.81)
  BOTTOM w0.135: v1(113.16,-30.56) 113.16,-29.01 112.84,-28.69 112.84,-27.13 114.75,-25.22 117.64,-25.22 117.92,-25.51 U32.5
BOOTMODE11: length 2.1
  TOP w0.135: R44.1 95.81,-28.16 v1(95.81,-28.16) 95.81,-28.84 R61.2
  BOTTOM w0.135: R204.2 95.86,-28.11 v1(95.81,-28.16)
BOOTMODE12: length 2.1
  TOP w0.135: R62.2 97.34,-28.17 v1(97.33,-28.17) 97.34,-28.16 R45.1
  BOTTOM w0.135: v1(97.33,-28.17) 97.41,-28.09 R203.2
BOOTMODE14: length 2.6
  TOP w0.135: R588.1 97.21,-33.5 v1(96.98,-33.73) R586.2
  BOTTOM w0.135: v1(96.98,-33.73) 96.98,-32.83 R589.2
BOOTMODE15: length 5.1
  TOP w0.135: R587.2 94.91,-34.12 v1(94.49,-33.7) 93.81,-33.7 93.31,-34.2 R590.1
  BOTTOM w0.135: v1(94.49,-33.7) 93.11,-33.7 R590.1
BOOTMODEON: length 4.6
  TOP w0.135: 35.05,-24.09 34.51,-24.09 33.94,-23.52 U4.22 ; 35.05,-24.09 R24.2 ; 35.05,-24.09 35.05,-23.45 35.26,-23.24 v1(35.51,-23.24)
  BOTTOM w0.135: U28.4 v1(35.51,-23.24)
BP_3V3: length 2.8
  TOP w0.508: R163.2 J5.1
BP_5V0: length 2.8
  TOP w0.508: R161.1 J5.2
BP_ADC0_AIN0: length 7.3
  TOP w0.135: J1.3 44.58,-59.92 44.58,-57.1 43.61,-56.13 R143.1
BP_ADC0_AIN1: length 7.4
  TOP w0.135: R152.1 55.96,-56.36 54.74,-57.58 54.74,-59.92 J1.11
BP_ADC0_AIN2: length 4.2
  TOP w0.135: R144.1 44.98,-56.06 45.83,-56.9 J1.6
BP_ADC0_AIN3: length 4.1
  TOP w0.135: R146.1 47.73,-56.82 48.37,-57.46 J1.8
BP_ADC0_AIN4: length 4
  TOP w0.135: J1.10 50.91,-57.46 50.47,-57.03 R148.1
BP_ADC0_AIN5: length 3.9
  TOP w0.135: R150.1 53.21,-56.23 53.45,-56.46 J1.12
BP_ADC0_AIN6: length 4.9
  TOP w0.135: R154.1 58.7,-55.96 J1.14
BP_ADC0_AIN7: length 5
  TOP w0.135: R156.1 61.44,-55.76 J1.16
BP_CONN_1_PORZ: length 27
  TOP w0.135: v1(26.26,-16.84) 26.26,-16.85 R8.1
  L03_SIG1 w0.127: J2.10 49.57,-14.15 37.66,-14.15 36.23,-15.58 29.02,-15.58 27.76,-16.84 v1(26.26,-16.84)
BP_CONN_2_PORZ: length 88.5
  TOP w0.135: R2.1 34.3,-14.59 v1(34.32,-14.58)
  L03_SIG1 w0.121: v1(34.32,-14.58) 36.14,-14.58 37.34,-13.39 75.11,-13.39 80.04,-18.31 83.74,-18.31 84.65,-19.22 97.2,-19.22 97.54,-19.56 100.33,-19.56 100.77,-19.12 100.77,-18.98 101.02,-18.73 101.16,-18.73 101.52,-18.36 101.52,-16.41 104.6,-13.33 112.25,-13.33 J6.10
BPSERVO_MUX_SEL: length 109.5
  TOP w0.135: v1(88.81,-56.81) 88.95,-56.81 88.99,-56.85 96.9,-56.85 97.73,-56.02 102.63,-56.02 103.3,-55.35 105.66,-55.35 106.03,-54.98 115.69,-54.98 116.2,-55.49 120.63,-55.49 121.31,-54.81 123.98,-54.81 124.58,-54.21 124.58,-54.21 v1(124.99,-53.8) 124.94,-53.8 124.87,-53.72 SW6.2 123.67,-52.14 123.77,-52.04 R598.1 ; v1(111.46,-21.84) 112.06,-21.23 119.68,-21.23 121.68,-23.23 121.69,-23.24 121.7,-23.25 121.7,-23.25 121.7,-24.91 121.6,-25.01 121.6,-25.76 122.01,-26.17 122.01,-27.01 v1(122.33,-27.33)
  BOTTOM w0.135: v1(122.33,-27.33) 122.33,-27.77 125.26,-30.71 129.36,-30.71 130.04,-31.39 130.04,-40.75 129.57,-41.22 129.57,-49.93 125.7,-53.8 v1(124.99,-53.8) 124.55,-53.8 124.49,-53.75 123.42,-53.75 121.64,-55.52 119.91,-55.52 119.59,-55.2 117.97,-55.2 117.81,-55.04 117.81,-54.23 118.16,-53.87 118.47,-53.87 118.49,-53.85 U52.15 ; U50.15 90.2,-59.64 89.23,-58.67 89.23,-57.23 v1(88.81,-56.81) ; U51.15 113.16,-22.79 113.11,-22.73 113.11,-22.07 112.7,-21.67 111.58,-21.67 111.46,-21.79 v1(111.46,-21.84)
CAP_VDDS0: length 1.1
  TOP w0.381: U18.D12 78.39,-43.73 v2(78.44,-43.77)
  BOTTOM w0.356: v2(78.44,-43.77) 78.35,-43.86 C192.1
CAP_VDDS1: length 1.5
  TOP w0.381: U18.N5 82.44,-46.81 v2(82.39,-46.77)
  BOTTOM w0.381: v2(82.39,-46.77) 82.39,-47.09 C233.1
CAP_VDDS2: length 1.3
  TOP w0.102: U18.U9 84.87,-44.81 84.61,-44.55 84.61,-44.52 v2(84.36,-44.27)
  BOTTOM w0.381: v2(84.36,-44.27) 84.18,-44.09 C196.1
CAP_VDDS3: length 1
  TOP w0.381: U18.R16 83.86,-41.35 v2(83.86,-41.75)
  BOTTOM w0.356: v2(83.86,-41.75) 83.66,-41.55 C173.1
CAP_VDDS4: length 2
  TOP w0.381: U18.N18 83.33,-40.32 v2(83.37,-40.35)
  BOTTOM w0.254: C149.1 83.26,-39.23 82.93,-39.56 82.93,-39.96 83.32,-40.35 v2(83.37,-40.35)
CAP_VDDS5: length 2.7
  TOP w0.381: U18.M18 v2(82.39,-40.86)
  BOTTOM w0.203: v2(82.39,-40.86) 82.39,-40.31 82.04,-39.95 82.04,-39.34 82.16,-39.22 C150.1
CAP_VDDS_MCU: length 1.6
  TOP w0.152: U18.D9 78.33,-44.81 v2(77.86,-45.28)
  BOTTOM w0.33: C223.1 77.24,-45.69 77.65,-45.28 v2(77.86,-45.28)
CORE_0V85_CT: length 2.9
  BOTTOM w0.254: C82.1 15.54,-16.97 16.24,-17.66 U27.2
CPSW_RGMII1_RD0: length 33.2
  TOP w0.102: U18.T5 84.39,-46.44 v2(84.38,-46.43)
  L03_SIG1 w0.121: v1(100.63,-50.5) 100.63,-51 100.76,-51.12 101.5,-51.12 101.75,-50.88 101.75,-49.75 101.5,-49.5 88.37,-49.5 87.5,-48.64 85.63,-48.64 84.38,-47.4 v2(84.38,-46.43)
  BOTTOM w0.135: v1(100.63,-50.5) 100.63,-51.73 100.77,-51.87 101.19,-51.87 101.32,-51.73 101.32,-50.19 102.01,-49.5 102.01,-48.67 104.33,-46.34 U40.28
CPSW_RGMII1_RD1: length 33.3
  TOP w0.102: 84.13,-49.66 84.13,-49.41 83.91,-49.19 83.91,-48.33 U18.R2
  TOP w0.135: 84.13,-49.66 84.13,-49.7 84.14,-49.71 84.14,-49.98 86.16,-51.99 86.16,-53.09 88.41,-55.34 100,-55.34 100.47,-54.88 100.66,-54.88 100.75,-54.97 100.94,-54.97 101.13,-54.78 101.13,-54.59 101.04,-54.5 101.04,-54.31 101.42,-53.92 v1(102.16,-53.92)
  BOTTOM w0.135: U40.26 104.71,-47.34 101.73,-50.32 101.73,-53.49 v1(102.16,-53.92)
CPSW_RGMII1_RD2: length 33.2
  TOP w0.102: 85.18,-49.42 85.17,-49.41 85.17,-48.59 U18.U2
  TOP w0.114: 85.42,-49.66 85.18,-49.42
  TOP w0.135: 85.42,-49.66 87.33,-51.56 87.33,-52.3 88.8,-53.77 95.73,-53.77 95.86,-53.64 95.86,-53.02 96,-52.88 96.27,-52.88 96.4,-53.02 96.4,-53.64 96.54,-53.77 96.81,-53.77 96.94,-53.64 96.94,-53.02 97.08,-52.88 97.34,-52.88 97.48,-53.02 97.48,-53.64 97.61,-53.77 97.88,-53.77 98.02,-53.64 98.02,-53.02 98.15,-52.88 98.42,-52.88 98.56,-53.02 98.56,-53.64 98.69,-53.77 98.96,-53.77 99.09,-53.64 99.09,-53.02 99.23,-52.88 99.5,-52.88 99.63,-53.02 99.63,-53.56 99.77,-53.7 100.23,-53.7 101.52,-52.4 v1(102.16,-52.4)
  BOTTOM w0.135: U40.24 105.08,-48.34 102.16,-51.26 v1(102.16,-52.4)
CPSW_RGMII1_RD3: length 33.2
  TOP w0.102: U18.T1 84.69,-49.11 84.69,-49.66
  TOP w0.135: v1(103.68,-53.92) 103.68,-54.45 103.82,-54.58 104.36,-54.58 104.5,-54.45 104.5,-53.59 104.32,-53.42 101.42,-53.42 100.36,-54.48 88.31,-54.48 86.72,-52.88 86.72,-51.74 84.69,-49.72 84.69,-49.66
  BOTTOM w0.135: U40.22 105.22,-49.34 102.92,-51.64 102.92,-53.16 v1(103.68,-53.92)
CPSW_RGMII1_RX_CTL: length 33.1
  TOP w0.102: 87.74,-48.65 87.38,-48.29 87.38,-48.12 87.08,-47.81 U18.Y3
  TOP w0.135: v1(105.21,-52.35) 108.85,-52.35 109.19,-52.01 109.19,-51.46 108.92,-51.18 97.76,-51.18 96.8,-50.22 89.31,-50.22 87.74,-48.65
  BOTTOM w0.135: v1(105.21,-52.35) 105.97,-52.35 107.75,-50.57 U40.20
CPSW_RGMII1_RXC: length 33.4
  TOP w0.102: 85.01,-49.66 84.89,-49.54 U18.U1
  TOP w0.135: 85.01,-49.66 87.05,-51.69 87.05,-52.58 88.65,-54.18 100.28,-54.18 101.31,-53.15 106.32,-53.15 106.48,-53.31 106.48,-53.79 106.34,-53.92 v1(105.21,-53.92)
  BOTTOM w0.135: v1(105.21,-53.92) 106.43,-53.92 108.75,-51.6 U40.18
CPSW_RGMII1_TD0: length 28.7
  TOP w0.102: 87.74,-42.15 87.23,-42.15 87.12,-42.04 86.67,-42.04 U18.Y14
  TOP w0.135: v1(106.17,-37.72) 105.39,-38.5 102.72,-38.5 102.12,-39.1 97.78,-39.1 97.76,-39.12 97.74,-39.12 94.71,-42.15 87.74,-42.15
  BOTTOM w0.135: v1(106.17,-37.72) 107.87,-37.72 108.25,-38.1 108.25,-38.99 108.41,-39.14 109.47,-39.14 109.6,-39.28 109.6,-39.78 109.47,-39.91 108.89,-39.91 108.75,-40.05 U40.42
CPSW_RGMII1_TD1: length 15.1
  TOP w0.102: 87.74,-41.61 86.69,-41.61 U18.Y16
  TOP w0.135: 87.74,-41.61 94.36,-41.61 97.85,-38.11 R596.1
CPSW_RGMII1_TD1_MUX: length 13.5
  TOP w0.135: R597.2 100.99,-36.91 101.3,-36.6 104.01,-36.6 104.14,-36.74 104.14,-37.58 104.01,-37.72 v1(103.5,-37.72)
  BOTTOM w0.135: U40.40 107.75,-40.2 106.16,-38.61 105.26,-38.61 105.12,-38.47 105.12,-38.03 104.99,-37.9 104.72,-37.9 104.58,-38.03 104.58,-38.47 104.45,-38.61 103.78,-38.61 103.5,-38.33 v1(103.5,-37.72)
CPSW_RGMII1_TD2: length 28.8
  TOP w0.102: U18.U13 v2(84.38,-43.33)
  L03_SIG1 w0.121: v1(101.78,-44.4) 99.95,-44.4 98.02,-42.47 87.27,-42.47 86.77,-42.98 84.79,-42.98 84.43,-43.33 v2(84.38,-43.33)
  BOTTOM w0.135: U40.37 105.72,-41.84 103.91,-40.03 102.04,-40.03 101.78,-40.29 v1(101.78,-44.4)
CPSW_RGMII1_TD3: length 28.7
  TOP w0.102: 87.74,-42.42 86.99,-42.42 U18.AA14
  TOP w0.135: v1(102.23,-40.51) 102.23,-39.5 102.1,-39.37 101.22,-39.37 101.08,-39.5 101.08,-39.92 100.95,-40.05 100.68,-40.05 100.54,-39.92 100.54,-39.5 100.41,-39.37 100.14,-39.37 100.01,-39.5 100.01,-39.92 99.87,-40.05 99.6,-40.05 99.47,-39.92 99.47,-39.5 99.33,-39.37 99.01,-39.37 98.88,-39.5 98.88,-40.22 98.74,-40.36 98.47,-40.36 98.34,-40.22 98.34,-39.5 98.2,-39.37 97.89,-39.37 97.66,-39.6 97.66,-40.11 97.53,-40.25 97.02,-40.25 94.89,-42.37 94.87,-42.37 94.82,-42.42 87.74,-42.42
  BOTTOM w0.135: v1(102.23,-40.51) 102.23,-41.45 102.39,-41.61 103.17,-41.61 103.31,-41.47 103.31,-41.13 103.44,-41 104.36,-41 104.65,-41.28 104.65,-42.44 105.04,-42.84 U40.35
CPSW_RGMII1_TX_CTL: length 26.4
  TOP w0.102: U18.W16 85.89,-41.74 v2(85.93,-41.77)
  L03_SIG1 w0.121: v2(85.93,-41.77) 86.45,-41.77 87.78,-40.44 95.79,-40.44 95.91,-40.32 95.91,-39.67 96.03,-39.55 96.27,-39.55 96.39,-39.67 96.39,-40.32 96.52,-40.44 96.76,-40.44 96.88,-40.32 96.88,-39.67 97,-39.55 97.24,-39.55 97.36,-39.67 97.36,-40.32 97.48,-40.44 97.72,-40.44 97.84,-40.32 97.84,-39.67 97.96,-39.55 98.2,-39.55 98.33,-39.67 98.33,-40.32 98.45,-40.44 98.69,-40.44 98.81,-40.32 98.81,-39.67 98.93,-39.55 99.17,-39.55 99.29,-39.67 99.29,-41.33 99.49,-41.53 100.8,-41.53 101.79,-42.52 v1(102.23,-42.52)
  BOTTOM w0.135: v1(102.23,-42.52) 102.23,-43.03 102.49,-43.28 R594.1
CPSW_RGMII1_TX_CTL_MUX: length 2.2
  BOTTOM w0.135: U40.33 104.86,-43.84 R595.2
CPSW_RGMII1_TXC: length 24.9
  L03_SIG1 w0.121: v1(104.71,-44.76) 103.88,-44.76 103.07,-45.57 99.54,-45.57 97.51,-43.54 96.22,-43.54 96.08,-43.67 96.08,-44.15 95.96,-44.27 95.72,-44.27 95.6,-44.15 95.6,-43.55 95.48,-43.43 95.24,-43.43 95.12,-43.55 95.12,-44.27 94.99,-44.39 94.75,-44.39 94.63,-44.27 94.63,-43.55 94.51,-43.43 94.27,-43.43 94.15,-43.55 94.15,-44.27 94.03,-44.39 93.79,-44.39 93.67,-44.27 93.67,-43.71 93.55,-43.59 91.3,-43.59 91.21,-43.68 v1(91.21,-44.12)
  BOTTOM w0.135: v1(91.21,-44.12) 90.63,-43.54 87.87,-43.54 R287.2 ; U40.31 104.79,-44.84 v1(104.71,-44.76)
DEBOUNCE_MCU_RESETZ: length 86.7
  TOP w0.135: U13.1 58.76,-35.04 58.76,-35.03 58.76,-35.01 58.75,-35 58.74,-34.99 57.73,-33.99 57.73,-33.55 57.73,-30.84 58.57,-30 66.47,-30 67.02,-29.45 67.02,-15.54 65.05,-13.56 32.46,-13.56 31.14,-14.88 26.44,-14.88 24.72,-13.17 SW2.3 23.53,-12 22.91,-11.38 20.78,-11.38 20.16,-12 SW2.1 18.02,-12 17.7,-12.32 D1.1 18.2,-13.29 18.53,-13.63 R1.1 C1.1
DEBOUNCE_SOC_RESET_REQZ: length 74.1
  TOP w0.135: C2.1 28.21,-13.87 28.2,-13.88 D2.1 v1(27.61,-12.9) SW3.1 28.77,-12 29.36,-11.4 31.57,-11.4 32.17,-12 SW3.3 64.2,-12 67.29,-15.09 67.29,-29.56 66.55,-30.3 61.19,-30.3 59.76,-31.73 U13.6
  BOTTOM w0.135: Q7.6 26.1,-14.05 Q7.8 26.1,-14.7 Q7.1 Q7.2 ; Q7.6 Q7.5 ; Q7.6 26.64,-13.45 26.82,-13.63 R170.1 27.61,-12.9 v1(27.61,-12.9)
DEBOUNCE_USER_INTN: length 48
  TOP w0.135: D4.1 75.05,-63.22 74.48,-63.79 SW5.1 73.62,-64.56 72.72,-65.46 71.04,-65.46 70.14,-64.56 SW5.3 67.71,-64.56 v1(67.46,-64.81) 66.72,-64.81 C78.1 66.26,-64.79 65.98,-64.51 R164.1 65.39,-64.51 64.82,-63.94 64.82,-56.72 63.55,-55.45 63.55,-52.12 60.32,-48.89 60.32,-43.69 61.03,-42.98 61.03,-38.23 59.76,-36.96 U13.3
  BOTTOM w0.135: v1(67.46,-64.81) 67.29,-64.97 Q16.2 Q16.1 65.57,-64.32 65.25,-64.65 Q16.8 64.88,-64.32 Q16.6 Q16.5
EEPROM_A1: length 2.3
  TOP w0.135: U17.2 64.04,-46.87 64.34,-47.17 R121.2
EEPROM_A2: length 2.6
  TOP w0.135: U17.3 64.69,-46.99 65.57,-47.87 R122.2
EEPROM_WP: length 2.8
  TOP w0.135: R89.1 64.88,-38.12 64.65,-38.35 64.39,-38.35 64.04,-38.7 U17.7
EHRPWM0_A: length 76
  TOP w0.102: U18.V21 85.39,-38.53 85.95,-37.97
  TOP w0.135: 85.95,-37.97 87.07,-36.86 87.07,-35.41 88.85,-33.63 90.4,-33.63 92.51,-31.52 92.94,-31.52 93.52,-30.94 v1(93.52,-27.61) 93.38,-27.46 R42.1
  L03_SIG1 w0.121: v1(93.52,-27.61) 93.52,-25.76 93.16,-25.4 92.81,-25.4 92.57,-25.65 92.57,-25.87 92.25,-26.18 91.9,-26.18 91.88,-26.16 91.37,-26.16 91.34,-26.19 90.57,-26.19 90.29,-25.91 90.27,-25.91 88.63,-24.27 88.58,-24.27 86.53,-22.22 80,-22.22 79.1,-21.31 71.68,-21.31 71.3,-21.69 69.01,-21.69 68.48,-21.16 64.59,-21.16 63.96,-21.79 44.51,-21.79 J2.1
EHRPWM0_B: length 79.6
  TOP w0.102: U18.U21 85.09,-38.62 85.09,-38.49 85.57,-38.01 85.57,-37.97
  TOP w0.135: R59.1 92.84,-29.83 v1(92.84,-30.81) 90.4,-33.25 88.75,-33.25 86.66,-35.33 86.66,-36.88 85.57,-37.97
  L03_SIG1 w0.121: J2.3 46.73,-21.48 63.91,-21.48 64.48,-20.91 68.59,-20.91 68.74,-21.06 69.12,-21.44 71.07,-21.44 71.45,-21.06 79.2,-21.06 80.11,-21.96 86.64,-21.96 88.45,-23.78 88.49,-23.78 90.37,-25.65 90.39,-25.65 90.68,-25.94 91.24,-25.94 92.05,-25.12 93.39,-25.12 93.64,-24.87 94.69,-24.87 95.15,-25.33 95.15,-25.81 96.27,-26.92 96.27,-27.98 96.97,-28.68 96.97,-29.13 96.57,-29.53 93.48,-29.53 92.84,-30.18 v1(92.84,-30.81)
EHRPWM0_TZN_IN0: length 87
  BOTTOM w0.135: U32.11 125.71,-24.86 126.03,-24.54 126.03,-21.51 123.29,-18.77 123.29,-14.71 121.02,-12.44 86.29,-12.44 84.15,-14.57 84.15,-15.41 82.75,-16.81 74.08,-16.81 71.44,-14.17 57.81,-14.17 57.25,-14.73 57.25,-16.15 56.84,-16.56 56.84,-17.18 J2.13
EHRPWM1_A: length 81.3
  TOP w0.102: U18.T20 84.39,-38.61 84.75,-38.25 84.75,-37.97
  TOP w0.135: R57.1 89.97,-29.9 v1(89.97,-30.81) 89.65,-31.13 89.65,-31.23 85.32,-35.56 85.32,-37.26 84.75,-37.83 84.75,-37.97
  L03_SIG1 w0.121: J2.5 49.02,-21.23 63.74,-21.23 64.31,-20.65 68.71,-20.65 69.24,-21.18 70.92,-21.18 71.3,-20.8 79.31,-20.8 79.62,-21.12 86.15,-21.12 88.56,-23.52 88.62,-23.52 90.78,-25.68 91.13,-25.68 91.95,-24.87 92.23,-24.87 92.48,-24.61 93.05,-24.61 93.12,-24.68 93.47,-24.68 93.54,-24.61 95.27,-24.61 97.76,-27.1 97.76,-28.7 96.67,-29.79 93.86,-29.79 93.32,-30.33 93.32,-30.93 93.01,-31.23 92.66,-31.23 92.13,-30.7 92.13,-30.29 91.78,-29.95 90.52,-29.95 89.97,-30.5 v1(89.97,-30.81)
EHRPWM1_B: length 58.6
  TOP w0.102: U18.T18 84.39,-40.35 v2(84.87,-40.82)
  TOP w0.135: J2.7 50.65,-20.32 63.58,-20.32 64.21,-19.68 v1(66.22,-19.68)
  L03_SIG1 w0.121: v2(84.87,-40.82) 84.96,-40.72 84.96,-38.79 85.27,-38.48 85.27,-33.4 v1(85.8,-32.87)
  BOTTOM w0.135: v1(85.8,-32.87) 86.87,-32.87 87.91,-31.83 87.91,-30.05 87.71,-29.85 R217.1 86.41,-29.85 86.16,-30.1 78.74,-30.1 76.12,-27.48 75.59,-27.48 67.79,-19.68 v1(66.22,-19.68)
EHRPWM2_A: length 57.9
  L03_SIG1 w0.121: J2.9 53.19,-20.32 63.85,-20.32 65.22,-18.95 68.94,-18.95 69.47,-19.48 72.97,-19.48 73.47,-19.98 78.39,-19.98 78.72,-19.65 83.42,-19.65 84.07,-20.29 87.93,-20.29 88.54,-20.9 90.08,-20.9 90.4,-20.57 96.24,-20.57 96.75,-21.08 v1(101.3,-21.08)
  BOTTOM w0.135: U30.3 102.06,-24.13 101.3,-23.37 v1(101.3,-21.08)
EHRPWM2_B: length 49.6
  L03_SIG1 w0.121: v1(89.64,-20.37) 89.26,-19.99 84.18,-19.99 83.58,-19.39 78.47,-19.39 78.14,-19.72 73.62,-19.72 72.53,-18.63 65.18,-18.63 63.74,-20.06 55.48,-20.06 J2.11
  BOTTOM w0.135: v1(89.64,-20.37) 91.8,-20.37 96.05,-24.63 U30.7
EPHY1_XI: length 2.7
  TOP w0.135: U7.20 139.18,-22.25 v1(138.79,-21.85) 138.79,-21.84 138.79,-21.84 R13.2
  BOTTOM w0.135: R13.2 138.79,-21.2 v1(138.79,-21.85)
EQEP1_A: length 24.5
  TOP w0.135: J12.1 157.46,-62.36 157.11,-62.01 C77.1
  BOTTOM w0.135: C77.1 156.51,-62.74 156.82,-63.04 157.05,-63.04 157.46,-63.45 J12.1 157.46,-65.86 157.15,-66.17 144.32,-66.17 143.73,-65.57 U46.16
EQEP1_A_LS: length 73.9
  TOP w0.102: 82.18,-49.66 82.18,-48.6 U18.L2
  TOP w0.135: v1(90.53,-58.39) 90.21,-58.71 86.6,-58.71 85.11,-57.22 85.11,-56.28 82.18,-53.35 82.18,-49.66
  L03_SIG1 w0.121: v1(90.53,-58.39) 99.34,-58.39 100.36,-57.38 106.09,-57.38 106.12,-57.41 106.68,-57.41 106.76,-57.33 138.07,-57.33 139.45,-58.71 139.45,-61.21 v1(142.23,-63.99)
  BOTTOM w0.135: U46.1 v1(142.23,-63.99)
EQEP1_B: length 19.8
  TOP w0.135: v1(145.62,-61.65) 145.62,-65.02 146.46,-65.86 153.7,-65.86 J12.2 154.92,-63.48 154.79,-63.35 C76.1
  BOTTOM w0.135: v1(145.62,-61.65) 145.56,-61.71 U46.14 ; C76.1 154.79,-63.34 154.92,-63.47 J12.2
EQEP1_B_LS: length 70.3
  TOP w0.102: U18.L3 82.35,-47.81 v2(82.39,-47.86)
  L03_SIG1 w0.121: v1(135.56,-56.34) 132.51,-56.34 131.19,-55.02 125.82,-55.02 124.95,-55.88 116.39,-55.88 115.15,-54.64 114.74,-54.64 114.2,-54.65 106.06,-54.65 105.36,-55.35 97.82,-55.35 96.53,-56.64 89.78,-56.64 89.23,-56.08 86.6,-56.08 83.74,-53.23 83.74,-50.62 82.39,-49.27 v2(82.39,-47.86)
  BOTTOM w0.135: v1(135.56,-56.34) 135.56,-57.2 140.06,-61.71 U46.3
EQEP1_I: length 14.4
  TOP w0.135: J12.3 152.38,-63.48 152.98,-62.88 C75.1
  BOTTOM w0.135: J12.3 152.38,-63.47 152.98,-62.87 C75.1 151.8,-62.01 150.99,-61.21 U46.13
EQEP1_I_LS: length 66.7
  TOP w0.102: v2(83.94,-47.29) 83.89,-47.23 U18.R5
  L03_SIG1 w0.121: v1(137.44,-54.08) 133.12,-54.08 132.16,-53.12 124.66,-53.12 124.59,-53.19 118.46,-53.19 117.23,-51.96 116.26,-51.96 115.78,-52.45 111.5,-52.45 110.46,-51.41 98.71,-51.41 97.57,-50.27 86.91,-50.27 v2(83.94,-47.29)
  BOTTOM w0.135: U46.4 140,-61.21 137.44,-58.65 v1(137.44,-54.08)
EQEP2_A: length 20.9
  TOP w0.135: J21.1 157.46,-57.15 156.51,-56.21 C73.1
  BOTTOM w0.135: C73.1 157.13,-55.66 157.46,-55.99 J21.1 157.46,-59.47 157.08,-59.84 152.27,-59.84 151.41,-60.71 U46.12
EQEP2_A_LS: length 123
  TOP w0.102: U18.B14 77.11,-42.59 76.22,-42.59 76.11,-42.48 76.05,-42.48
  TOP w0.135: v1(68.3,-62.15) 67.06,-62.15 65.49,-60.59 65.49,-56.45 64.82,-55.78 64.82,-52.58 60.86,-48.62 60.86,-44.2 63.37,-41.68 66.96,-41.68 68.17,-42.89 70.9,-42.89 71.32,-42.47 76.05,-42.47 76.05,-42.48
  L03_SIG1 w0.121: v1(68.3,-62.15) 71.07,-59.39 88.31,-59.39 88.47,-59.55 88.49,-59.55 88.76,-59.82 88.76,-59.84 89.01,-60.09 89.03,-60.09 93.97,-65.03 118.55,-65.03 120.56,-63.01 137.6,-63.01 138.67,-61.94 138.67,-58.81 v1(138.35,-58.5)
  BOTTOM w0.135: v1(138.35,-58.5) 138.35,-58.94 140.11,-60.71 U46.5
EQEP2_B: length 16.4
  TOP w0.135: C72.1 154.79,-57 154.92,-57.13 J21.2
  BOTTOM w0.135: U46.11 151.35,-60.21 152.02,-59.54 153.67,-59.54 J21.2 154.79,-58.16 C72.1
EQEP2_B_LS: length 95.8
  L03_SIG1 w0.121: v1(93.42,-52.68) 97.64,-52.68 99.57,-54.61 105.73,-54.61 105.95,-54.39 113.74,-54.39 114.3,-54.39 114.74,-54.39 115.26,-54.39 116.5,-55.63 124.84,-55.63 125.71,-54.76 131.37,-54.76 132.44,-55.83 138.35,-55.83 v1(140.26,-57.73)
  BOTTOM w0.135: R244.2 71.17,-40.94 70.31,-41.81 68.17,-41.81 67.15,-42.83 67.15,-50.52 68.32,-51.69 71.95,-51.69 74.65,-54.38 85.81,-54.38 86.29,-53.89 87.8,-53.89 88.44,-54.53 91.57,-54.53 v1(93.42,-52.68) ; U46.6 140.37,-60.21 139.75,-59.59 139.75,-58.24 v1(140.26,-57.73)
EQEP2_I: length 14
  TOP w0.135: C71.1 152.98,-56.53 152.38,-57.13 J21.3
  BOTTOM w0.135: C71.1 152.98,-56.52 152.38,-57.12 J21.3 150.97,-59.71 U46.10
EQEP2_I_LS: length 20.8
  TOP w0.135: U22.3 v1(154.58,-50.9)
  BOTTOM w0.135: U46.7 140.55,-59.71 140.18,-59.34 140.18,-58.52 141.68,-57.02 147.37,-57.02 153.49,-50.9 v1(154.58,-50.9)
FB_1V1: length 3.1
  BOTTOM w0.203: U39.8 125.73,-43.89
  BOTTOM w0.381: R248.2 126.32,-43.89 125.73,-43.89
  BOTTOM w0.508: R248.2 R247.1
FB_2V5: length 3.1
  BOTTOM w0.203: U33.8 125.73,-33.17
  BOTTOM w0.381: R233.2 126.32,-33.17 125.73,-33.17
  BOTTOM w0.508: R233.2 R232.1
FSI/BP_MUX_SEL: length 35.8
  TOP w0.102: 86.82,-37.97 86.57,-38.22 86.54,-38.22 86.53,-38.23 86.29,-38.23 85.91,-38.62 85.91,-39.3 U18.W20
  TOP w0.135: R61.1 95.81,-29.83 v1(95.81,-30.81) 95.81,-31.29 94.03,-33.07 91.72,-33.07 90.35,-34.44 88.98,-34.44 87.81,-35.61 87.81,-36.96 86.82,-37.95 86.82,-37.97
  L03_SIG1 w0.121: v1(104.39,-29.71) 103.72,-30.39 97.16,-30.39 96.73,-30.81 v1(95.81,-30.81)
  BOTTOM w0.135: U30.1 104.44,-23.13 104.84,-23.54 R190.2 106.42,-23.54 106.93,-24.05 106.93,-27.17 v1(104.39,-29.71)
FSI_RX0_CLK: length 27.4
  BOTTOM w0.135: U30.2 102.23,-23.63 102.08,-23.49 102.08,-22.91 102.28,-22.71 102.28,-17.67 98.39,-13.78 88.73,-13.78 87.76,-14.76 87.76,-16.74 J16.1
FSI_RX0_D0: length 10.9
  BOTTOM w0.135: J16.5 91.55,-19.74 96.04,-24.23 97.72,-24.23 97.83,-24.13 U30.8
FSI_RX0_D1: length 48
  TOP w0.135: v1(122.3,-25.3) 122.3,-23.06 119.88,-20.64 115.3,-20.64 v1(114.99,-20.32) 114.67,-20.64 109.77,-20.64 108.37,-22.04 102.35,-22.04 v1(101.85,-22.54)
  BOTTOM w0.135: v1(122.3,-25.3) 122.75,-25.3 122.96,-25.51 U32.12 ; v1(114.99,-20.32) 115.48,-20.82 U51.4 ; J16.7 93.26,-17.21 93.26,-16.45 92.86,-16.05 92.86,-14.76 93.57,-14.05 97.24,-14.05 101.85,-18.66 v1(101.85,-22.54)
FSI_RX0CLK_PWM2A: length 27.3
  TOP w0.135: v1(122.68,-26.46) 121.87,-25.65 121.87,-25.12 122.03,-24.96 122.03,-23.17 119.77,-20.91 109.9,-20.91 108.53,-22.28 108.51,-22.3 108.5,-22.3 108.49,-22.3 108.47,-22.31 106.14,-22.31 v1(104.39,-24.05)
  BOTTOM w0.135: v1(122.68,-26.46) 123,-26.78 123.07,-26.78 123.1,-26.81 U32.14 ; v1(104.39,-24.05) 104.39,-24.45 104.21,-24.63 U30.4
FSI_RX0D0_PWM2B: length 51.6
  TOP w0.135: v1(121.58,-26.44) 121.58,-27.41 120.16,-28.83 112.27,-28.83 112.14,-28.95 112.14,-29.64 112.19,-29.69 v1(112.19,-30.45)
  L03_SIG1 w0.121: v1(112.19,-30.45) 110.08,-32.56 107.72,-32.56 104.82,-29.66 104.82,-29.53 104.57,-29.28 101.75,-29.28 100.91,-30.13 97.05,-30.13 96.8,-30.39 94.11,-30.39 93.83,-30.67 93.83,-31.14 92.86,-32.11 v1(92.53,-32.11)
  BOTTOM w0.135: U32.13 123.52,-26.16 123.35,-25.98 122.04,-25.98 v1(121.58,-26.44) ; U30.6 94.33,-25.13 93.07,-26.39 93.07,-29.44 92.33,-30.18 92.33,-31.62 v1(92.53,-32.11)
FSI_TX0_CLK: length 54.6
  TOP w0.102: 83.87,-37.97 83.87,-38.17 83.59,-38.46 83.59,-38.62 U18.P21
  TOP w0.135: 83.87,-37.97 83.87,-35.28 85.29,-33.86 85.29,-30.45 85.84,-29.91 85.84,-22.82 87.71,-20.95 ; 87.71,-20.95 87.71,-16.73 J16.2 ; 87.71,-20.95 88.54,-20.95 88.55,-20.96 88.57,-20.96 88.58,-20.97 88.59,-20.97 89,-21.39 90.09,-21.39 90.64,-20.84 90.65,-20.83 90.67,-20.83 100.51,-20.83 101.28,-20.05 106.64,-20.05 v1(106.96,-20.37)
  BOTTOM w0.135: v1(106.96,-20.37) 107.49,-20.9 108.2,-20.9 108.71,-20.4 109.07,-20.4 109.3,-20.62 113.3,-20.62 114.28,-21.61 U51.1
FSI_TX0_D0: length 73.9
  TOP w0.102: 87.74,-39.91 87.74,-39.92 87.48,-40.18 87.48,-40.19 87.35,-40.32 U18.Y18
  TOP w0.135: v1(98.78,-29.69) 98.93,-29.84 98.93,-32.74 97.69,-33.99 97.69,-35.31 97.45,-35.55 R586.1 96.98,-36.6 v1(96.95,-36.63) 93.93,-36.63 93.27,-37.29 90.36,-37.29 87.74,-39.91
  BOTTOM w0.135: v1(96.95,-36.63) 94.72,-36.63 93.39,-37.95 93.39,-40.02 95.08,-41.71 95.08,-51.65 95.54,-52.11 95.54,-59.44 95.66,-59.56 95.66,-60.52 94.46,-61.72 92.2,-61.72 91.82,-61.34 U50.11 ; J16.6 91.55,-15.65 92.79,-16.89 92.79,-19.74 94.53,-21.48 98.49,-21.48 99.83,-22.82 99.83,-25.57 98.2,-27.2 98.2,-29.11 v1(98.78,-29.69)
FSI_TX0_D1: length 36.1
  TOP w0.102: U18.AA19 87.52,-39.19
  TOP w0.114: 87.52,-39.19 87.65,-39.06
  TOP w0.135: v1(98.78,-28.37) 98.25,-28.91 98.25,-30.68 97.69,-31.24 96.77,-31.24 96.29,-31.72 96.29,-34.74 95.86,-35.17 R587.1 94.56,-35.17 92.98,-36.75 89.96,-36.75 87.65,-39.06
  BOTTOM w0.135: v1(98.78,-28.37) 98.78,-27.13 100.18,-25.73 100.18,-22.78 98.62,-21.22 98.6,-21.21 98.58,-21.21 97.41,-21.21 95.38,-19.18 95.38,-16.8 95.38,-16.79 95.36,-16.77 J16.8
